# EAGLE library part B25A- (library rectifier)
RECTIFIER 25-A bridge
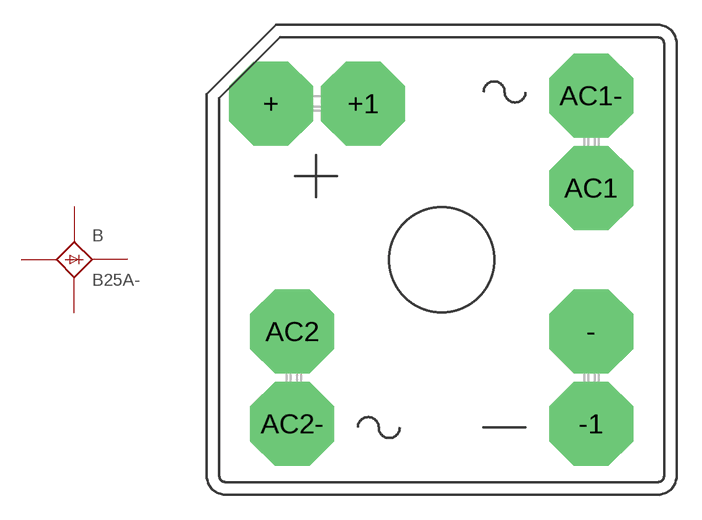
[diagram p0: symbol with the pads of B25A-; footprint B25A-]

Designator prefix B

## B25A-  [B25A-]
+  +  pas
+1  +  pas
-  -  pas
-1  -  pas
AC1  AC1  pas
AC1-  AC1  pas
AC2  AC2  pas
AC2-  AC2  pas

## Footprint B25A- (pad centres in mm)
RECTIFIER 25-A bridge
drill 2.007 pad 5.08 octagon: + -10.338,9.449; +1 -4.75,9.449; - 9.042,-4.343; -1 9.042,-9.931; AC1 9.042,4.343; AC1- 9.042,9.931; AC2 -9.042,-4.343; AC2- -9.042,-9.931
hole 6.401 at 0,0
